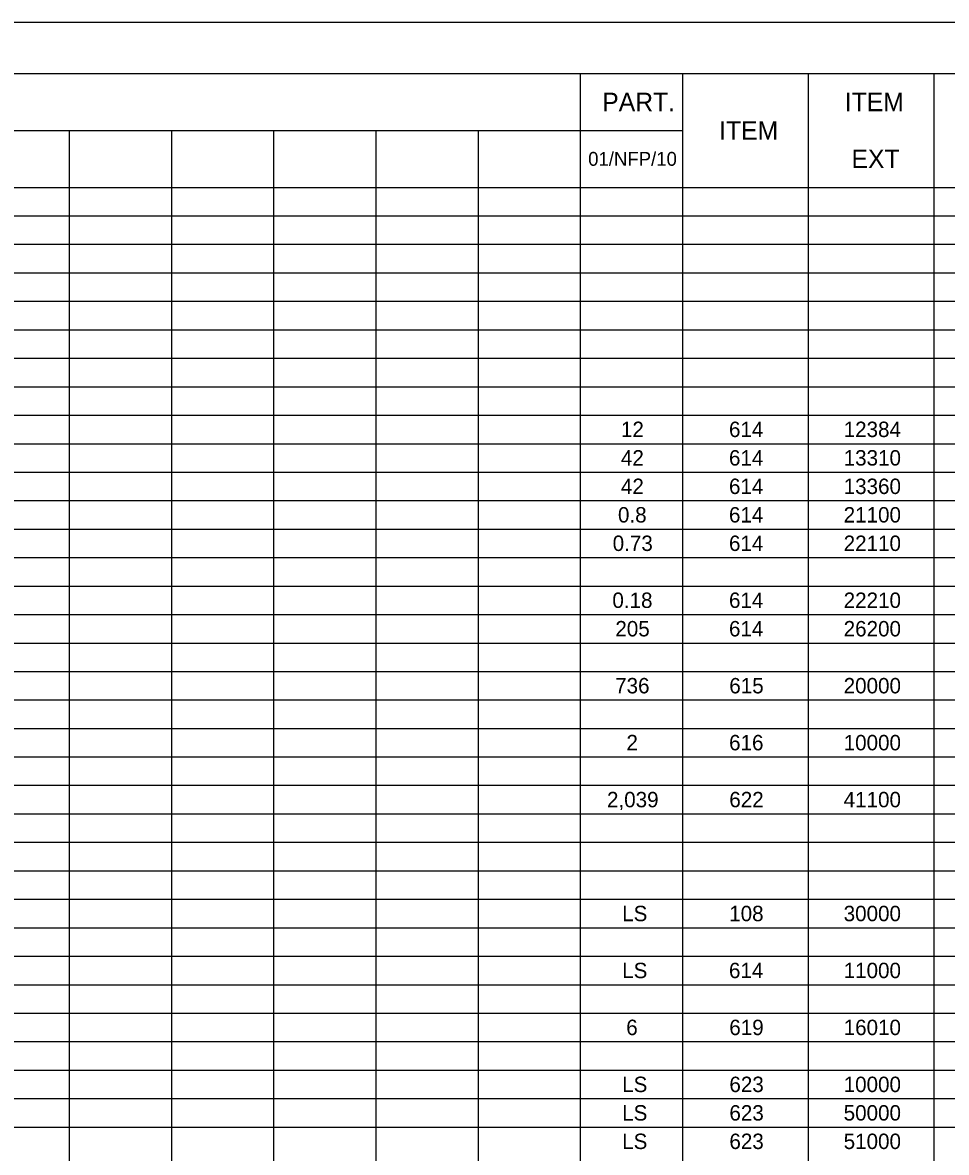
# Model space of a CAD drawing. Extents: x -50.3 to 36.4, y 0 to 22.5.
# Drawn here: x 9.08 to 18.16, y 10.89 to 22 of the extents above; entities that cross this region are included whole.
import ezdxf

# ---------------------------------------------------------------- set-up
doc = ezdxf.new("R2010")
doc.units = 0
for name, color, linetype in [('SH_Border', 7, 'Continuous'), ('SH_Cut_Line', 7, 'Continuous'), ('SH_Data', 7, 'Continuous'), ('SH_Text', 7, 'Continuous')]:
    doc.layers.add(name, color=color, linetype=linetype)

msp = doc.modelspace()

# ---------------------------------------------------------------- linework, layer by layer
at = {"layer": 'SH_Border'}
msp.add_lwpolyline([(1.5, 21.5), (33.5, 21.5), (33.5, 0.5), (1.5, 0.5)], close=True, dxfattribs=at)
at = {"layer": 'SH_Cut_Line'}
msp.add_lwpolyline([(0, 0), (34, 0), (34, 22), (0, 22)], close=True, dxfattribs=at)
at = {"layer": 'SH_Data'}
for p, q in [((1.5, 21.5), (32.001, 21.5)), ((14.56, 21.5), (14.56, 0.502)), ((15.565, 21.5), (15.565, 0.502)), ((16.8, 21.5), (16.8, 0.502)), ((18.035, 21.5), (18.035, 0.502)), ((1.5, 20.94), (15.565, 20.94)), ((9.537, 20.94), (9.537, 0.502)), ((10.542, 20.94), (10.542, 0.502)), ((11.546, 20.94), (11.546, 0.502)), ((12.551, 20.94), (12.551, 0.502)), ((13.556, 20.94), (13.556, 0.502)), ((1.5, 20.38), (32.001, 20.38)), ((1.5, 20.1), (32.001, 20.1)), ((1.5, 19.82), (32.001, 19.82)), ((1.5, 19.54), (32.001, 19.54)), ((1.5, 19.26), (32.001, 19.26)), ((1.5, 18.98), (32.001, 18.98)), ((1.5, 18.7), (32.001, 18.7)), ((1.5, 18.42), (32.001, 18.42)), ((1.5, 18.14), (32.001, 18.14)), ((1.5, 17.86), (32.001, 17.86)), ((1.5, 17.58), (32.001, 17.58)), ((1.5, 17.3), (32.001, 17.3)), ((1.5, 17.02), (32.001, 17.02)), ((1.5, 16.74), (32.001, 16.74)), ((1.5, 16.46), (32.001, 16.46)), ((1.5, 16.18), (32.001, 16.18)), ((1.5, 15.9), (32.001, 15.9)), ((1.5, 15.62), (32.001, 15.62)), ((1.5, 15.34), (32.001, 15.34)), ((1.5, 15.061), (32.001, 15.061)), ((1.5, 14.781), (32.001, 14.781)), ((1.5, 14.501), (32.001, 14.501)), ((1.5, 14.221), (32.001, 14.221)), ((1.5, 13.941), (32.001, 13.941)), ((1.5, 13.661), (32.001, 13.661)), ((1.5, 13.381), (32.001, 13.381)), ((1.5, 13.101), (32.001, 13.101)), ((1.5, 12.821), (32.001, 12.821)), ((1.5, 12.541), (32.001, 12.541)), ((1.5, 12.261), (32.001, 12.261)), ((1.5, 11.981), (32.001, 11.981)), ((1.5, 11.701), (32.001, 11.701)), ((1.5, 11.421), (32.001, 11.421)), ((1.5, 11.141), (32.001, 11.141))]:
    msp.add_line(p, q, dxfattribs=at)

# ---------------------------------------------------------------- texts
at = {"layer": 'SH_Text'}
for s, height, p in [('PART.', 0.1818, (14.776, 21.129)), ('ITEM', 0.1818, (17.16, 21.129)), ('ITEM', 0.1818, (15.925, 20.849)), ('01/NFP/10', 0.1364, (14.638, 20.592)), ('EXT', 0.1818, (17.226, 20.569)), ('12', 0.1515, (14.96, 17.925)), ('614', 0.1515, (16.022, 17.925)), ('12384', 0.1515, (17.149, 17.925)), ('42', 0.1515, (14.96, 17.645)), ('614', 0.1515, (16.022, 17.645)), ('13310', 0.1515, (17.149, 17.645)), ('42', 0.1515, (14.96, 17.365)), ('614', 0.1515, (16.022, 17.365)), ('13360', 0.1515, (17.149, 17.365)), ('0.8', 0.1515, (14.931, 17.085)), ('614', 0.1515, (16.022, 17.085)), ('21100', 0.1515, (17.149, 17.085)), ('0.73', 0.1515, (14.879, 16.805)), ('614', 0.1515, (16.022, 16.805)), ('22110', 0.1515, (17.149, 16.805)), ('0.18', 0.1515, (14.876, 16.245)), ('614', 0.1515, (16.022, 16.245)), ('22210', 0.1515, (17.149, 16.245)), ('205', 0.1515, (14.905, 15.965)), ('614', 0.1515, (16.022, 15.965)), ('26200', 0.1515, (17.149, 15.965)), ('736', 0.1515, (14.903, 15.405)), ('615', 0.1515, (16.025, 15.405)), ('20000', 0.1515, (17.149, 15.405)), ('2', 0.152, (15.014, 14.845)), ('616', 0.1515, (16.023, 14.845)), ('10000', 0.1515, (17.149, 14.845)), ('2,039', 0.1515, (14.823, 14.285)), ('622', 0.1515, (16.025, 14.285)), ('41100', 0.1515, (17.149, 14.285)), ('LS', 0.1515, (14.972, 13.165)), ('108', 0.1515, (16.024, 13.165)), ('30000', 0.1515, (17.149, 13.165)), ('LS', 0.1515, (14.972, 12.605)), ('614', 0.1515, (16.022, 12.605)), ('11000', 0.1515, (17.149, 12.605)), ('6', 0.152, (15.012, 12.045)), ('619', 0.1515, (16.025, 12.045)), ('16010', 0.1515, (17.149, 12.045)), ('LS', 0.1515, (14.972, 11.485)), ('623', 0.1515, (16.026, 11.485)), ('10000', 0.1515, (17.149, 11.485)), ('LS', 0.1515, (14.972, 11.205)), ('623', 0.1515, (16.026, 11.205)), ('50000', 0.1515, (17.149, 11.205)), ('LS', 0.1515, (14.972, 10.925)), ('623', 0.1515, (16.026, 10.925)), ('51000', 0.1515, (17.149, 10.925))]:
    msp.add_text(s, height=height, dxfattribs=at).set_placement(p)

doc.saveas('drawing.dxf')
